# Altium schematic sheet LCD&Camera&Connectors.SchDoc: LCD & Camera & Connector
size A4; DocumentNumber: MB1165; Revision: C.1; SheetNumber: 6; SheetTotal: 17; Project: STM32469I-EVAL
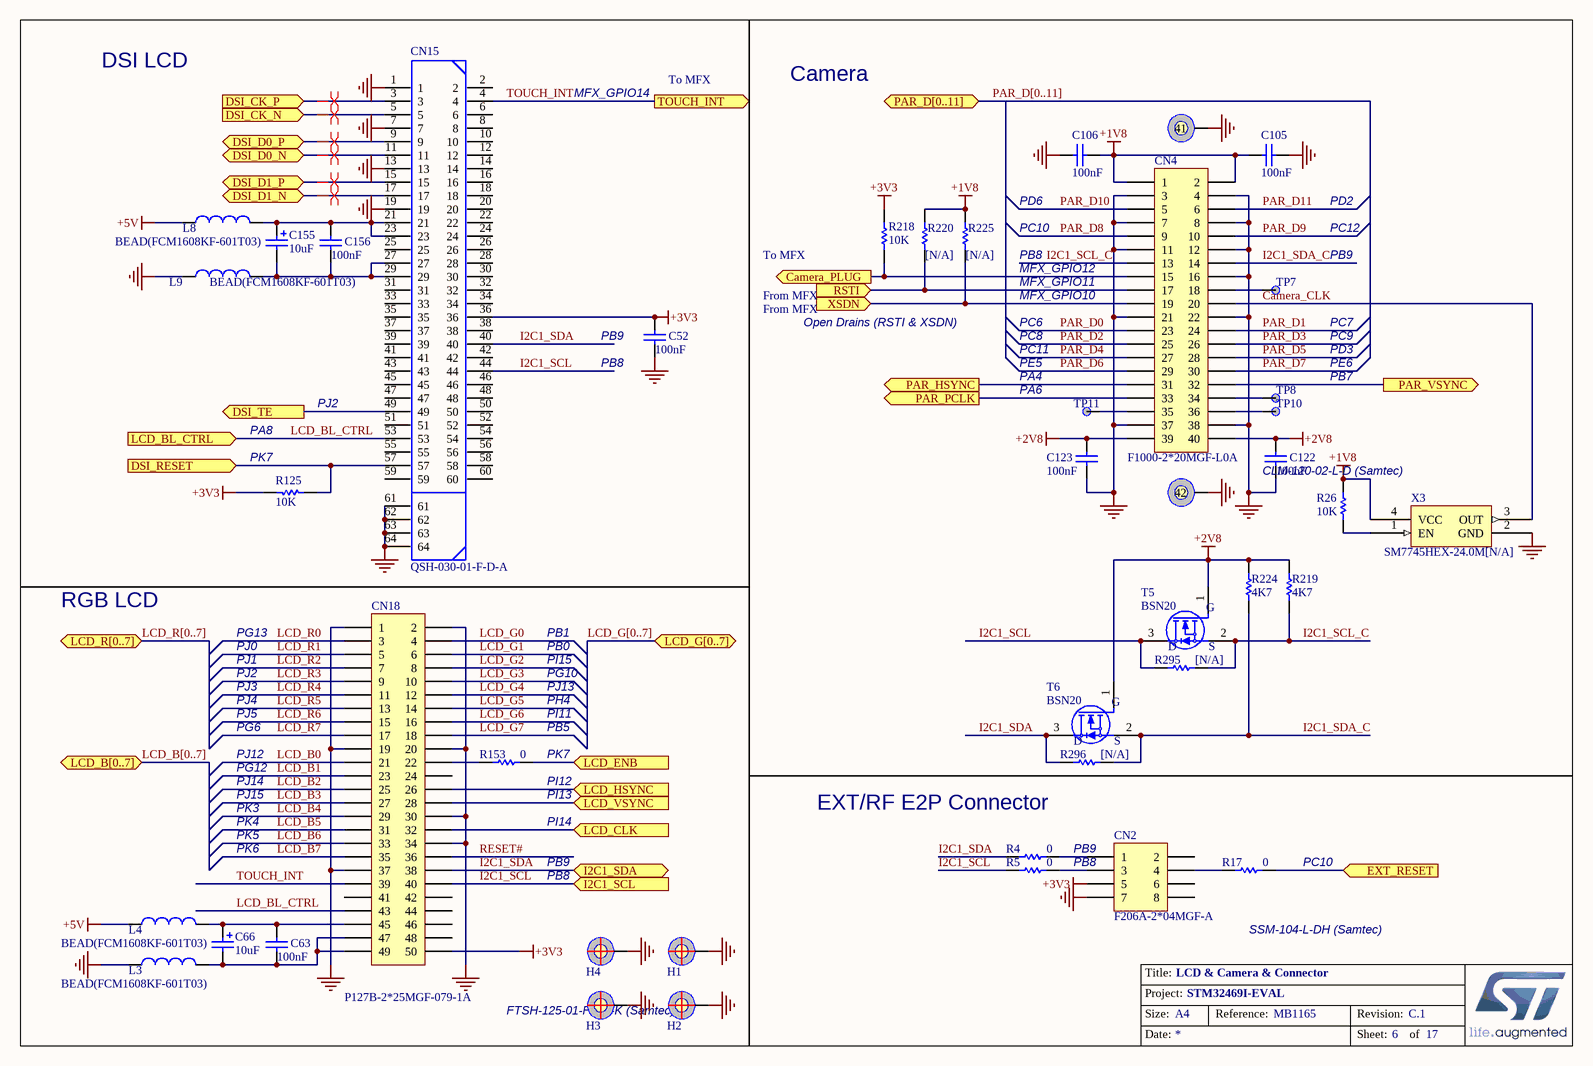
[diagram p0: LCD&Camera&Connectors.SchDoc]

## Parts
C52  100nF  [0603C]
C63  100nF  [0603C]
C66  10uF  [TAN-A]
C105  100nF  [0603C]
C106  100nF  [0603C]
C122  100nF  [0603C]
C123  100nF  [0603C]
C155  10uF  [TAN-A]
C156  100nF  [0603C]
CN2  F206A-2*04MGF-A  [SSM-104-L-DH]
CN4  F1000-2*20MGF-L0A  [CLM-120-02-L-D]
CN15  QSH-030-01-F-D-A  [QSH-030-01-F-D-A]
CN18  P127B-2*25MGF-079-1A  [FTSH-125-01-F-DV]
H1  POSITION HOLE  [HOLE_C9D4R5]  (value not drawn)
H2  POSITION HOLE  [HOLE_C9D4R5]  (value not drawn)
H3  POSITION HOLE  [HOLE_C9D4R5]  (value not drawn)
H4  POSITION HOLE  [HOLE_C9D4R5]  (value not drawn)
L3  BEAD(FCM1608KF-601T03)  [0603L]
L4  BEAD(FCM1608KF-601T03)  [0603L]
L8  BEAD(FCM1608KF-601T03)  [0603L]
L9  BEAD(FCM1608KF-601T03)  [0603L]
R4  0  [0603R]
R5  0  [0603R]
R17  0  [0603R]
R26  10K  [0402R]
R125  10K  [0603R]
R153  0  [0603R]
R218  10K  [0603R]
R219  4K7  [0603R]
R220  [N/A]  [0603R]
R224  4K7  [0603R]
R225  [N/A]  [0603R]
R295  [N/A]  [0603R]
R296  [N/A]  [0603R]
T5  BSN20  [SOT-23]
T6  BSN20  [SOT-23]
TP7  (no value)  [TP]
TP8  (no value)  [TP]
TP10  (no value)  [TP]
TP11  (no value)  [TP]
X3  SM7745HEX-24.0M[N/A]  [OSC_4SM_7X5]

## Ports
Camera_PLUG (out), DSI_CK_N (in), DSI_CK_P (in), DSI_D0_N (bidir), DSI_D0_P (bidir), DSI_D1_N (bidir), DSI_D1_P (bidir), DSI_RESET (in), DSI_TE (out), EXT_RESET (in), I2C1_SCL (in), I2C1_SDA (bidir), LCD_B[0..7] (bidir), LCD_BL_CTRL (in), LCD_CLK (in), LCD_ENB (in), LCD_G[0..7] (bidir), LCD_HSYNC (in), LCD_R[0..7] (bidir), LCD_VSYNC (in), PAR_D[0..11] (bidir), PAR_HSYNC (out), PAR_PCLK (out), PAR_VSYNC (out), RSTI (in), TOUCH_INT (out), XSDN (in)

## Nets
+1V8: C105.1 C106.2 CN4.1 CN4.2 R26.2 R220.2 R225.2 X3.4(VCC)
+2V8: C122.1 C123.1 CN4.39 CN4.40 R219.2 R224.2 T5.1(G) T6.1(G)
+3V3: C52.1 CN2.5 CN15.36 CN18.50 R125.2 R218.1
+5V: L4.1 L8.1
GND: C52.2 C105.2 C106.1 C122.2 C123.2 CN2.7 CN4.3 CN4.4 CN4.7 CN4.8 CN4.11 CN4.12 CN4.16 CN4.21 CN4.22 CN4.37 CN4.38 CN4.41 CN4.42 CN15.1 CN15.7 CN15.13 CN15.19 CN15.61 CN15.62 CN15.63 CN15.64 CN18.1 CN18.2 CN18.19 CN18.20 CN18.30 CN18.34 CN18.37 H1.1 H2.1 H3.1 H4.1 L3.1 L9.1 X3.2(GND)
Camera_CLK: CN4.20 X3.3(OUT)
Camera_PLUG: CN4.15 R218.2 ; port Camera_PLUG
DSI_CK_N: CN15.5 ; port DSI_CK_N
DSI_CK_P: CN15.3 ; port DSI_CK_P
DSI_D0_N: CN15.11 ; port DSI_D0_N
DSI_D0_P: CN15.9 ; port DSI_D0_P
DSI_D1_N: CN15.17 ; port DSI_D1_N
DSI_D1_P: CN15.15 ; port DSI_D1_P
DSI_RESET: CN15.57 R125.1 ; port DSI_RESET
DSI_TE: CN15.49 ; port DSI_TE
EXT_RESET: R17.2 ; port EXT_RESET
I2C1_SCL: CN15.44 CN18.40 R5.1 R295.1 T5.3(D) ; port I2C1_SCL
I2C1_SCL_C: CN4.13 R219.1 R295.2 T5.2(S)
I2C1_SDA: CN15.40 CN18.38 R4.1 R296.1 T6.3(D) ; port I2C1_SDA
I2C1_SDA_C: CN4.14 R224.1 R296.2 T6.2(S)
LCD_B0: CN18.21
LCD_B1: CN18.23
LCD_B2: CN18.25
LCD_B3: CN18.27
LCD_B4: CN18.29
LCD_B5: CN18.31
LCD_B6: CN18.33
LCD_B7: CN18.35
LCD_BL_CTRL: CN15.53 CN18.43 ; port LCD_BL_CTRL
LCD_CLK: CN18.32 ; port LCD_CLK
LCD_ENB: R153.2 ; port LCD_ENB
LCD_G0: CN18.4
LCD_G1: CN18.6
LCD_G2: CN18.8
LCD_G3: CN18.10
LCD_G4: CN18.12
LCD_G5: CN18.14
LCD_G6: CN18.16
LCD_G7: CN18.18
LCD_HSYNC: CN18.26 ; port LCD_HSYNC
LCD_R0: CN18.3
LCD_R1: CN18.5
LCD_R2: CN18.7
LCD_R3: CN18.9
LCD_R4: CN18.11
LCD_R5: CN18.13
LCD_R6: CN18.15
LCD_R7: CN18.17
LCD_VSYNC: CN18.28 ; port LCD_VSYNC
PAR_D0: CN4.23
PAR_D1: CN4.24
PAR_D2: CN4.25
PAR_D3: CN4.26
PAR_D4: CN4.27
PAR_D5: CN4.28
PAR_D6: CN4.29
PAR_D7: CN4.30
PAR_D8: CN4.9
PAR_D9: CN4.10
PAR_D10: CN4.5
PAR_D11: CN4.6
PAR_HSYNC: CN4.31 ; port PAR_HSYNC
PAR_PCLK: CN4.33 ; port PAR_PCLK
PAR_VSYNC: CN4.32 ; port PAR_VSYNC
RESET#: CN18.36
RSTI: CN4.17 R220.1 ; port RSTI
TOUCH_INT: CN15.4 CN18.39 ; port TOUCH_INT
XSDN: CN4.19 R225.1 ; port XSDN
NetC63_1: C63.1 C66.1 CN18.45 L4.2
NetC63_2: C63.2 C66.2 CN18.47 CN18.49 L3.2
NetC155_1: C155.1 C156.1 CN15.21 CN15.23 L8.2
NetC155_2: C155.2 C156.2 CN15.27 CN15.29 L9.2
NetCN2_1: CN2.1 R4.2
NetCN2_3: CN2.3 R5.2
NetCN2_4: CN2.4 R17.1
NetCN4_18: CN4.18 TP7.1
NetCN4_34: CN4.34 TP8.1
NetCN4_35: CN4.35 TP11.1
NetCN4_36: CN4.36 TP10.1
NetCN18_22: CN18.22 R153.1
NetR26_1: R26.1 X3.1(EN)

Not connected (* = marked no-connect by the designer): CN2 2 6 8; CN15 2 6 8 10 12 14 16 18 20 22 24 25 26 28 30 31 32 33 34 35 37 38 39 41 42 43 45 46 47 48 50 51 52 54 55 56 58 59 60; CN18 24 41 42 44 46 48

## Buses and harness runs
bus LCD_B[0..7] = port LCD_B[0..7]
bus LCD_G[0..7] = port LCD_G[0..7]
bus LCD_R[0..7] = port LCD_R[0..7]
bus PAR_D[0..11] = port PAR_D[0..11]

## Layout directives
differential pair: DSI_CK_N, DSI_CK_P, DSI_D0_N, DSI_D0_P, DSI_D1_N, DSI_D1_P

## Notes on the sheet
- DSI LCD
- MFX_GPIO14
- To MFX
- Camera
- PC10
- PB8
- PD6
- PB9
- PD2
- PC12
- From MFX
- Open Drains (RSTI & XSDN)
- PC6
- MFX_GPIO12
- MFX_GPIO10
- MFX_GPIO11
- PC7
- (near C52) PB9
- (near C52) PB8
- PC11
- PE5
- PA4
- PA6
- PC8
- PE6
- PC9
- PB7
- PD3
- PA8
- (near R125) PK7
- PJ2
- (near CN4) CLM-120-02-L-D (Samtec)
- RGB LCD
- PG13
- PJ0
- PJ1
- PB1
- PB0
- PI15
- PJ3
- PJ4
- PJ5
- PG6
- PG10
- PJ13
- PH4
- (near R153) PI11
- (near R153) PB5
- PJ12
- PG12
- PJ14
- PJ15
- (near R153) PK7
- (near R153) PI12
- (near R153) PI13
- PK3
- PK4
- PK5
- PK6
- PI14
- EXT/RF E2P Connector
- (near R17) PC10
- (near CN2) SSM-104-L-DH (Samtec)
- FTSH-125-01-F-DV-K (Samtec)

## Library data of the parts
C52 C63 C105 C106 C122 C123 C156 = Cap: Capacitor; Value: 10nF
C66 C155 = Cap Pol1: Polarized Capacitor (Radial)
CN2 = SSM-104-L-DH: Header, 5-Pin, Dual row
CN4 = CLM-120-02-L-D: Header, 20-Pin, Dual row
CN15 = QSH-030-01-F-D-A: HIGH SPEED SOCKET STRIP, .5mm PITCH, 60 PINS; MANUFACTURER: SAMTEC; PCB DECAL: QSH-030-01-X-D-A
CN18 = Header 25X2: Header, 26-Pin, Dual row
L3 L4 L8 L9 = Inductor: Value: 100uH
R4 R5 R17 R26 R125 R153 R218 R295 R296 = Res1: Resistor; Value: 1K
R219 R220 R224 R225 = res1: Resistor; Value: 1K
T5 T6 = 2N7000
TP7 TP8 TP10 TP11 = TP
X3 = SM7745HEV-50.0M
